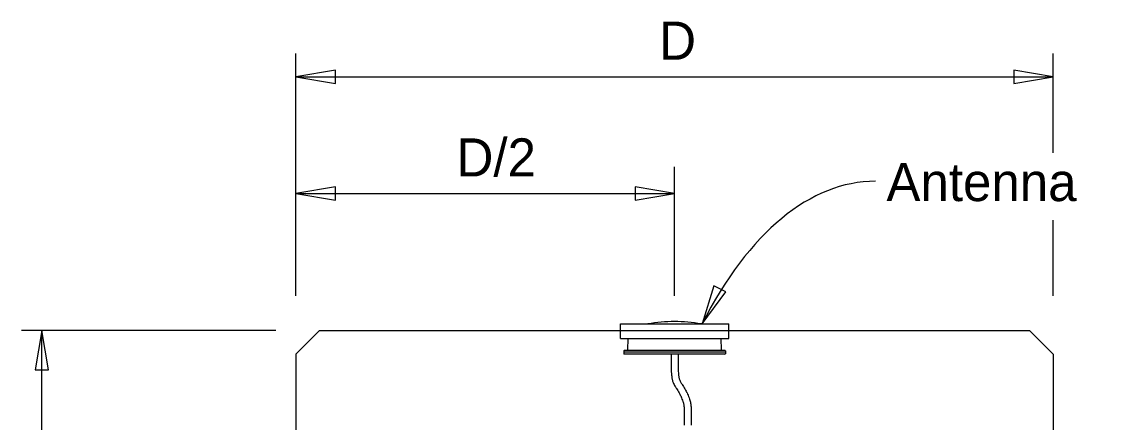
# Model space of a CAD drawing. Extents: x 0 to 36.1, y -3.7 to 15.
# Drawn here: x 1.568 to 4.42, y 8.036 to 9.096 of the extents above; entities that cross this region are included whole.
import ezdxf

# ---------------------------------------------------------------- set-up
doc = ezdxf.new("R2010")
doc.units = 0
for name, color, linetype in [('AdhocPoint_dp', 7, 'Continuous'), ('Leader', 7, 'Continuous'), ('Miscellaneous', 7, 'Continuous'), ('PileConc', 7, 'Continuous'), ('PlotBorder_dp', 7, 'Continuous')]:
    doc.layers.add(name, color=color, linetype=linetype)

msp = doc.modelspace()

# ---------------------------------------------------------------- linework, layer by layer
at = {"layer": 'Leader'}
msp.add_ellipse((3.8235, 7.3647), major_axis=(0, -1.3086), ratio=0.497877, start_param=3.141593, end_param=3.920397, dxfattribs=at)
msp.add_spline([(4.7543, 8.0608), (4.6955, 8.0608), (4.6085, 8.0412), (4.5454, 7.9672), (4.528, 7.8301), (4.5389, 7.7126), (4.491, 7.6017), (4.4083, 7.5603), (4.3343, 7.5516), (4.1994, 7.5821), (4.0906, 7.6474), (4.062, 7.6683)], degree=3, dxfattribs=at)
at = {"layer": 'Miscellaneous'}
for p, q in [((3.1499, 8.2961), (3.1915, 8.2961)), ((3.1499, 8.2786), (3.1499, 8.2961)), ((3.1499, 8.2578), (3.1499, 8.2786)), ((3.1499, 8.2786), (3.1915, 8.2786)), ((3.1915, 8.2961), (3.3946, 8.2961)), ((3.1915, 8.2786), (3.3946, 8.2786)), ((3.2228, 8.2962), (3.2228, 8.2961)), ((3.3633, 8.2962), (3.3633, 8.2961)), ((3.3946, 8.2961), (3.4362, 8.2961)), ((3.3946, 8.2786), (3.4362, 8.2786)), ((3.4362, 8.2786), (3.4362, 8.2961)), ((3.4362, 8.2578), (3.4362, 8.2786)), ((3.1499, 8.2578), (3.1915, 8.2578)), ((3.1693, 8.2277), (3.1701, 8.2578)), ((3.1915, 8.2578), (3.3946, 8.2578)), ((3.3946, 8.2578), (3.4362, 8.2578)), ((3.4167, 8.2277), (3.416, 8.2578)), ((3.159, 8.2253), (3.1589, 8.2213)), ((3.1915, 8.2213), (3.1589, 8.2213)), ((3.1589, 8.2213), (3.159, 8.2173)), ((3.1603, 8.2265), (3.1915, 8.2265)), ((3.1915, 8.2161), (3.1603, 8.2161)), ((3.1915, 8.2265), (3.3946, 8.2265)), ((3.3946, 8.2213), (3.1915, 8.2213)), ((3.3946, 8.2161), (3.1915, 8.2161)), ((3.3946, 8.2265), (3.4258, 8.2265)), ((3.4272, 8.2213), (3.3946, 8.2213)), ((3.4258, 8.2161), (3.3946, 8.2161)), ((3.4271, 8.2253), (3.4272, 8.2213)), ((3.4272, 8.2213), (3.4271, 8.2173))]:
    msp.add_line(p, q, dxfattribs=at)
for centre, radius, start, end in [((3.293, 7.8985), 0.4038, 79.9853, 100.0147), ((3.293, 7.8985), 0.4038, 100.0147, 100.0917), ((3.293, 7.8985), 0.4038, 79.9083, 79.9853), ((3.1603, 8.2253), 0.00125, 90, 178.5), ((3.1603, 8.2174), 0.00125, 181.5, 270), ((3.1681, 8.2278), 0.00125, 270, 358.5), ((3.418, 8.2278), 0.00125, 181.5, 270), ((3.4258, 8.2253), 0.00125, 1.5, 90), ((3.4258, 8.2174), 0.00125, 270, 358.5)]:
    msp.add_arc(centre, radius, start, end, dxfattribs=at)
for points in [[(3.2837, 8.2161), (3.2837, 8.2001), (3.2833, 8.1837), (3.2849, 8.1627), (3.2853, 8.1585), (3.2861, 8.1521), (3.2866, 8.1495), (3.2879, 8.1446), (3.2887, 8.1423), (3.2916, 8.1357), (3.2939, 8.1316), (3.2986, 8.1243), (3.3008, 8.1212), (3.3065, 8.1117), (3.3099, 8.1045), (3.3154, 8.0902), (3.3174, 8.0831), (3.3182, 8.0745), (3.3183, 8.0728), (3.3183, 8.0694), (3.3183, 8.067), (3.3183, 8.061), (3.3183, 8.0488), (3.3183, 8.0367), (3.3183, 8.0286)], [(3.3022, 8.2161), (3.3022, 8.1998), (3.3018, 8.1838), (3.3033, 8.1644), (3.3037, 8.1605), (3.3045, 8.1548), (3.3047, 8.1534), (3.3055, 8.1504), (3.3061, 8.1489), (3.3093, 8.1411), (3.3141, 8.135), (3.323, 8.1201), (3.3267, 8.1122), (3.3331, 8.0958), (3.3356, 8.0872), (3.3367, 8.0757), (3.3368, 8.0734), (3.3368, 8.0688), (3.3368, 8.067), (3.3368, 8.061), (3.3368, 8.0488), (3.3368, 8.0367), (3.3368, 8.0286)]]:
    msp.add_open_spline(points, degree=3, dxfattribs=at)
at = {"layer": 'PileConc'}
for p, q in [((2.293, 8.2161), (2.3555, 8.2786)), ((2.3555, 8.2786), (4.2305, 8.2786)), ((4.2305, 8.2786), (4.293, 8.2161)), ((2.293, 8.2161), (2.293, 6.3411)), ((4.293, 8.2161), (4.293, 6.3411))]:
    msp.add_line(p, q, dxfattribs=at)
at = {"layer": 'PlotBorder_dp'}
for p, q in [((2.293, 8.3704), (2.293, 9.0116)), ((4.293, 8.7487), (4.293, 9.0116)), ((2.293, 8.9498), (4.293, 8.9498)), ((3.293, 8.3704), (3.293, 8.7119)), ((2.293, 8.641), (3.293, 8.641)), ((4.293, 8.3704), (4.293, 8.5702)), ((2.2394, 8.2786), (1.5682, 8.2786)), ((1.6218, 6.2786), (1.6218, 8.2786))]:
    msp.add_line(p, q, dxfattribs=at)
for points in [[(2.293, 8.9498), (2.3972, 8.9321), (2.3972, 8.9674)], [(4.293, 8.9498), (4.1889, 8.9674), (4.1889, 8.9321)], [(2.293, 8.641), (2.3972, 8.6233), (2.3972, 8.6586)], [(3.293, 8.641), (3.1889, 8.6586), (3.1889, 8.6233)], [(3.3658, 8.2961), (3.4285, 8.3811), (3.397, 8.397)], [(1.6218, 8.2786), (1.6042, 8.1745), (1.6395, 8.1745)]]:
    msp.add_lwpolyline(points, close=True, dxfattribs=at)

# ---------------------------------------------------------------- texts
at = {"layer": 'AdhocPoint_dp'}
for s, p in [('D', (3.2524, 8.9948)), ('D/2', (2.7171, 8.686))]:
    msp.add_text(s, height=0.1008, dxfattribs=at).set_placement(p)
at = {"layer": 'PlotBorder_dp'}
msp.add_text('Antenna', height=0.1008, dxfattribs=at).set_placement((3.8526, 8.6209))

doc.saveas('drawing.dxf')
